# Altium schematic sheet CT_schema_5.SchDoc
size 257 x 245 mm
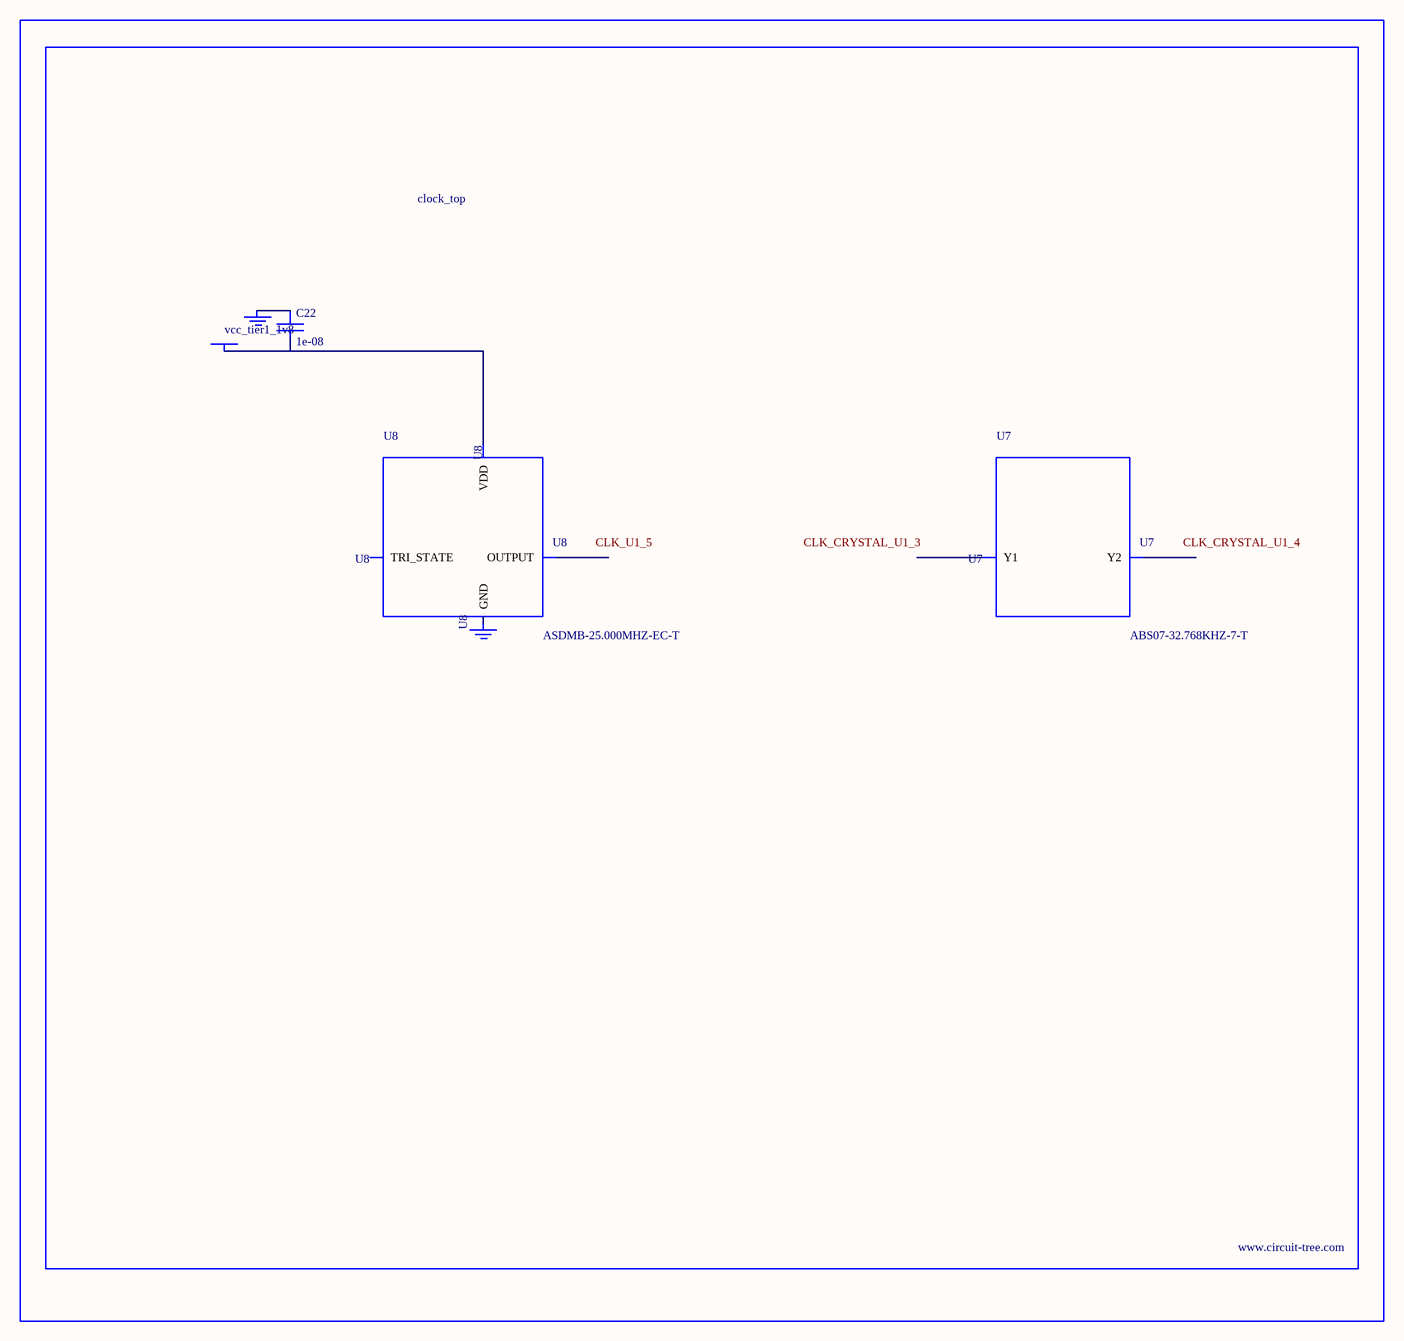
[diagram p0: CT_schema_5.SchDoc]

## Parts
BORDER4  (no value)
C22  1e-08  [C0402]
GND_INSTANCE_4_0  (no value)
GND_INSTANCE_4_1  (no value)
POWER_INSTANCE_4_0  vcc_tier1_1v8
U7  ABS07-32.768KHZ-7-T  [ABS07-32.768KHZ-7-T]
U8  ASDMB-25.000MHZ-EC-T  [ASDMB-XX.XXXXMHZ-XX-XX-XXX]

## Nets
NetC22_1: C22.1 GND_INSTANCE_4_0.0(GND)
NetC22_2: C22.2 POWER_INSTANCE_4_0.0(PWR) U8.4(VDD)

Not connected (* = marked no-connect by the designer): GND_INSTANCE_4_1 0(GND); U7 1(Y1) 2(Y2); U8 1(TRI_STATE) 2(GND) 3(OUTPUT)

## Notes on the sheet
- Labels drawn without touching a wire or pin: CLK_CRYSTAL_U1_3, CLK_CRYSTAL_U1_4, CLK_U1_5

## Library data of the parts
BORDER4 = BORDER_PAGE4
C22 = C0402C103K3RAC
GND_INSTANCE_4_0 GND_INSTANCE_4_1 = GND
POWER_INSTANCE_4_0 = PWR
